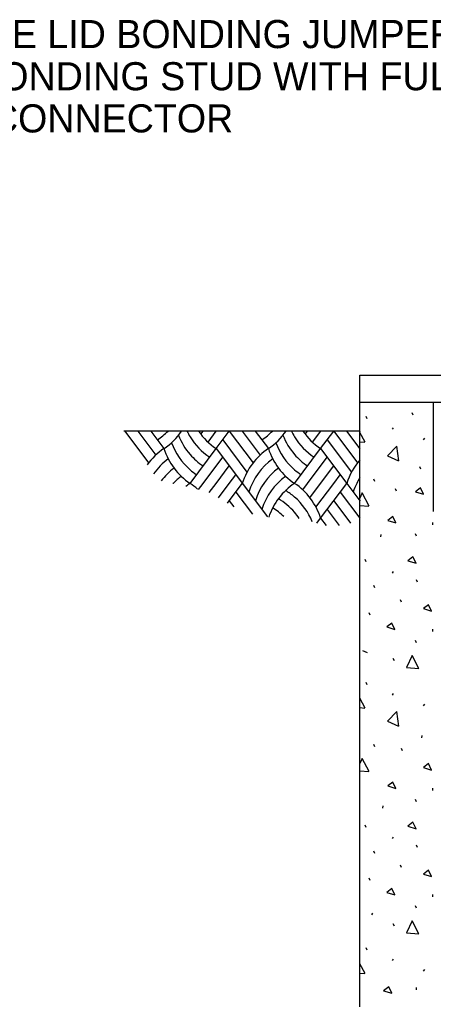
# Model space of a CAD drawing. Extents: x 99862 to 103151, y 100000 to 102076.
# Drawn here: x 100886 to 101121, y 100438 to 100996 of the extents above; entities that cross this region are included whole.
import ezdxf

# ---------------------------------------------------------------- set-up
doc = ezdxf.new("R2010")
doc.units = 0
for name, color, linetype in [('Level 1', 7, 'Continuous'), ('Level 12', 7, 'Continuous'), ('Level 13', 7, 'Continuous'), ('Level 14', 7, 'Continuous'), ('Level 2', 7, 'Continuous'), ('Level 20', 7, 'Continuous'), ('Level 3', 7, 'Continuous')]:
    doc.layers.add(name, color=color, linetype=linetype)

msp = doc.modelspace()

# ---------------------------------------------------------------- linework, layer by layer
at = {"layer": 'Level 1'}
msp.add_line((101079.24, 100395.52), (101079.24, 100778.02), dxfattribs=at)
at = {"layer": 'Level 12'}
msp.add_arc((100880.84, 100550.17), 393.6, 270.6995, 0.6995, dxfattribs=at)
at = {"layer": 'Level 13'}
for p, q in [((101079.24, 100761.58), (100944.95, 100761.58)), ((100945.48, 100761.58), (100959.06, 100743.47)), ((100952.9, 100761.58), (100963.14, 100747.93)), ((100960.33, 100761.58), (100967.79, 100751.62)), ((100988.76, 100759.78), (100990.11, 100761.58)), ((100992.83, 100755.32), (100997.53, 100761.58)), ((100997.49, 100751.62), (101004.95, 100761.58)), ((101004.88, 100761.58), (101018.46, 100743.47)), ((101012.3, 100761.58), (101022.54, 100747.93)), ((101019.73, 100761.58), (101027.2, 100751.62)), ((101048.16, 100759.78), (101049.51, 100761.58)), ((101052.24, 100755.32), (101056.93, 100761.58)), ((101056.89, 100751.62), (101064.36, 100761.58)), ((101071.7, 100761.58), (101079.24, 100751.52)), ((101079.13, 100761.58), (101079.24, 100761.42)), ((101001.2, 100756.57), (101015.01, 100738.16)), ((101060.61, 100756.57), (101074.42, 100738.16)), ((101064.32, 100761.52), (101077.86, 100743.47)), ((100982.64, 100731.82), (100997.49, 100751.62)), ((100997.49, 100751.62), (101026.69, 100712.69)), ((101042.04, 100731.82), (101056.89, 100751.62)), ((101056.89, 100751.62), (101071.74, 100731.82)), ((100990.06, 100731.82), (101001.2, 100746.67)), ((101049.47, 100731.82), (101060.61, 100746.67)), ((100997.49, 100731.82), (101004.91, 100741.72)), ((101056.89, 100731.82), (101064.32, 100741.72)), ((101004.91, 100731.82), (101008.63, 100736.77)), ((101064.32, 100731.82), (101068.03, 100736.77)), ((100987.46, 100728.36), (100990.06, 100731.82)), ((100993.56, 100726.58), (100997.49, 100731.82)), ((100998.73, 100723.58), (101004.91, 100731.82)), ((101003.9, 100720.57), (101012.34, 100731.82)), ((101046.7, 100728.13), (101049.47, 100731.82)), ((101050.78, 100723.67), (101056.89, 100731.82)), ((101054.22, 100718.36), (101064.32, 100731.82)), ((101056.89, 100712.03), (101071.74, 100731.82)), ((101071.74, 100731.82), (101079.24, 100721.82)), ((101008.64, 100726.87), (101018.06, 100714.31)), ((101068.03, 100726.87), (101079.24, 100711.92)), ((101004.92, 100721.92), (101007.53, 100718.45)), ((101060.61, 100716.98), (101067.39, 100707.92)), ((101064.32, 100721.92), (101073.85, 100709.21)), ((101054.79, 100709.22), (101056.89, 100712.03)), ((101056.89, 100712.03), (101060.03, 100707.85))]:
    msp.add_line(p, q, dxfattribs=at)
for centre, start, end in [((100939.41, 100792.71), 303.9036, 304.0531), ((100943.12, 100787.76), 303.9036, 315.8293), ((100946.83, 100782.81), 303.9036, 325.5924), ((101014.74, 100777.86), 205.6807, 211.332), ((101018.45, 100782.81), 214.4076, 236.0964), ((100998.81, 100792.71), 303.9036, 304.0531), ((101002.52, 100787.76), 303.9036, 315.8293), ((101006.23, 100782.81), 303.9036, 325.5924), ((101074.14, 100777.86), 205.6807, 211.332), ((101077.85, 100782.81), 214.4076, 236.0964), ((101058.21, 100792.71), 303.9036, 304.0465), ((101011.03, 100772.91), 201.4344, 220.9416), ((101014.74, 100777.86), 211.3319, 236.0964), ((101070.43, 100772.91), 201.4344, 220.9416), ((101074.14, 100777.86), 211.3319, 236.0964), ((100988.75, 100720.44), 123.9036, 144.2873), ((101003.6, 100763.01), 197.6434, 236.0964), ((101007.31, 100767.96), 200.2432, 228.9599), ((101048.16, 100720.44), 123.9036, 162.3685), ((101063.01, 100763.01), 197.6434, 236.0964), ((101066.72, 100767.96), 200.2432, 228.9599), ((100992.46, 100715.49), 126.3063, 144.6719), ((101011.02, 100772.91), 220.9415, 236.0964), ((101051.87, 100715.49), 126.3063, 162.3685), ((101070.43, 100772.91), 220.9415, 236.0964), ((101107.55, 100720.44), 138.878, 162.3566), ((100996.18, 100710.54), 127.1006, 142.8865), ((101007.31, 100767.96), 228.9599, 236.0964), ((101055.58, 100710.54), 127.1006, 162.3685), ((101066.72, 100767.96), 228.9599, 236.0964), ((100999.89, 100705.59), 126.331, 135.7128), ((101059.29, 100705.59), 126.331, 162.3685), ((101111.26, 100715.49), 148.441, 154.2266), ((100999.89, 100705.59), 135.7127, 135.9946), ((101003.6, 100700.64), 123.9036, 128.557), ((100961.68, 100700.64), 47.8269, 56.0963), ((101063.01, 100700.64), 123.9036, 161.4903), ((101021.08, 100700.64), 17.6434, 56.0963), ((101111.26, 100715.49), 154.2265, 162.3566), ((101013.66, 100690.74), 40.9413, 59.3021), ((101017.37, 100695.69), 48.9597, 58.5465), ((101017.37, 100695.69), 22.2387, 48.9597), ((101009.95, 100685.79), 46.1934, 58.4874), ((101114.98, 100710.54), 161.9697, 162.3566), ((101013.66, 100690.74), 34.1792, 40.9414)]:
    msp.add_arc(centre, 37.58, start, end, dxfattribs=at)
at = {"layer": 'Level 14'}
for p, q in [((101083.45, 100768.52), (101082.86, 100769.84)), ((101109.61, 100770.73), (101109.02, 100772.05)), ((101098.18, 100763.51), (101097.59, 100762.63)), ((101115.9, 100757.49), (101115.32, 100756.61)), ((101113.94, 100739.83), (101113.36, 100741.15)), ((101087.75, 100732.92), (101087.17, 100734.24)), ((101100.13, 100727.41), (101099.54, 100728.73)), ((101120.63, 100709.48), (101120.48, 100708.17)), ((101091.15, 100702.77), (101091.01, 100701.45)), ((101111.49, 100701.71), (101110.9, 100703.03)), ((101082.78, 100687.11), (101082.2, 100688.43)), ((101098.18, 100681.57), (101097.59, 100680.69)), ((101087.75, 100672.28), (101087.17, 100673.59)), ((101112.04, 100675.64), (101111.45, 100676.96)), ((101102.92, 100664.27), (101102.33, 100665.59)), ((101085.05, 100656.8), (101084.46, 100658.12)), ((101120.63, 100648.84), (101120.48, 100647.52)), ((101111.49, 100641.07), (101110.9, 100642.39)), ((101098.83, 100630.83), (101098.24, 100632.15)), ((101083.45, 100617.16), (101082.86, 100618.47)), ((101098.18, 100612.15), (101097.59, 100611.27)), ((101115.9, 100606.12), (101115.32, 100605.24)), ((101087.75, 100581.8), (101087.17, 100583.12)), ((101114.49, 100588.2), (101114.34, 100586.88)), ((101103.42, 100579.55), (101102.84, 100580.87)), ((101120.63, 100558.37), (101120.48, 100557.05)), ((101111.49, 100550.59), (101110.9, 100551.91)), ((101092.32, 100548.32), (101092.17, 100547)), ((101082.78, 100536), (101082.2, 100537.31)), ((101098.18, 100530.46), (101097.59, 100529.58)), ((101087.75, 100521.16), (101087.17, 100522.48)), ((101112.04, 100524.53), (101111.45, 100525.85)), ((101102.92, 100513.16), (101102.33, 100514.48)), ((101085.05, 100505.68), (101084.46, 100507)), ((101120.63, 100497.73), (101120.48, 100496.41)), ((101111.49, 100489.95), (101110.9, 100491.27)), ((101086.47, 100487.15), (101085.88, 100486.27)), ((101098.83, 100479.72), (101098.24, 100481.04)), ((101083.45, 100466.04), (101082.86, 100467.36)), ((101098.18, 100461.03), (101097.59, 100460.15)), ((101115.9, 100455.01), (101115.32, 100454.13)), ((101111.33, 100444.92), (101111.18, 100443.6))]:
    msp.add_line(p, q, dxfattribs=at)
for points in [[(101082.21, 100755.27), (101079.24, 100760.86)], [(101079.24, 100755.51), (101082.06, 100755.27)], [(101101.42, 100744.62), (101100.26, 100753), (101095.01, 100747.58), (101101.28, 100744.67)], [(101115.48, 100725.58), (101113.72, 100729.24), (101110.79, 100727.05), (101115.48, 100725.58)], [(101084.5, 100718.88), (101080.55, 100726.35), (101079.24, 100723.44)], [(101079.24, 100719.31), (101084.36, 100718.88)], [(101099.76, 100709.26), (101098.01, 100712.92), (101095.07, 100710.72), (101099.76, 100709.26)], [(101111.2, 100686.32), (101109.44, 100689.99), (101106.51, 100687.79), (101111.2, 100686.32)], [(101120.05, 100659.09), (101118.3, 100662.75), (101115.37, 100660.55), (101120.05, 100659.09)], [(101099.19, 100648.61), (101097.43, 100652.28), (101094.5, 100650.08), (101099.19, 100648.61)], [(101080.79, 100636.71), (101083.3, 100635.55)], [(101112.86, 100626.45), (101108.9, 100633.92), (101105.83, 100627.03), (101112.71, 100626.45)], [(101082.21, 100603.91), (101079.24, 100609.5)], [(101079.24, 100604.15), (101082.06, 100603.91)], [(101101.42, 100593.51), (101100.26, 100601.88), (101095.01, 100596.46), (101101.28, 100593.56)], [(101084.5, 100567.76), (101080.55, 100575.23), (101079.24, 100572.32)], [(101120.05, 100568.62), (101118.3, 100572.28), (101115.37, 100570.08), (101120.05, 100568.62)], [(101079.24, 100568.2), (101084.36, 100567.76)], [(101099.76, 100558.14), (101098.01, 100561.81), (101095.07, 100559.61), (101099.76, 100558.14)], [(101111.2, 100535.21), (101109.44, 100538.87), (101106.51, 100536.67), (101111.2, 100535.21)], [(101120.05, 100507.97), (101118.3, 100511.64), (101115.37, 100509.44), (101120.05, 100507.97)], [(101099.19, 100497.5), (101097.43, 100501.16), (101094.5, 100498.97), (101099.19, 100497.5)], [(101112.86, 100475.33), (101108.9, 100482.81), (101105.83, 100475.92), (101112.71, 100475.33)], [(101082.21, 100452.79), (101079.24, 100458.38)], [(101079.24, 100453.03), (101082.06, 100452.79)], [(101097.37, 100441.56), (101095.61, 100445.22), (101092.68, 100443.03), (101097.37, 100441.56)]]:
    msp.add_lwpolyline(points, dxfattribs=at)
at = {"layer": 'Level 2'}
msp.add_line((101121.05, 100715.75), (101121.05, 100778.02), dxfattribs=at)
at = {"layer": 'Level 3'}
for p, q in [((101079.24, 100778.02), (101079.24, 100793.49)), ((101079.24, 100793.49), (101140.74, 100793.49)), ((101079.24, 100778.02), (102059.12, 100778.02))]:
    msp.add_line(p, q, dxfattribs=at)

# ---------------------------------------------------------------- texts
at = {"layer": 'Level 20'}
for s, p in [(' 4   ROUTE LID BONDING JUMPER', (100784.91, 100979.59)), ('TO LID BONDING STUD WITH FULL ', (100784.91, 100955.59)), ('CIRCLE CONNECTOR', (100784.91, 100931.59))]:
    msp.add_text(s, height=16, dxfattribs=at).set_placement(p)

doc.saveas('drawing.dxf')
